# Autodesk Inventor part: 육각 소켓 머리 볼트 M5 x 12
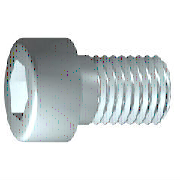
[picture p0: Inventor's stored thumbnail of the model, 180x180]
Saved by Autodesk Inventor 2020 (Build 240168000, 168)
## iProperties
Created: 2012-02
Part Number: 육각 소켓 머리 볼트 M5 x 12
Material: 강철, 연강
Description: 6각 소켓 머리 캡 나사
Document SubType Name: Modeling
Standard: ISO 4762
Designer: mdu-01
Standard Revision: Fourth edition 2004-03-01
Standards Organization: ISO
Language: ko-KR
Size Designation: M5 x 12
Categories: <MemberInstance><Categories><Category DisplayName="조임쇠" InternalName="e4da775c-781d-43d5-af7c-5136215cf5a6" Mnemonic="FSTN"><Category DisplayName="볼트" InternalN
Density: 7.86 g/cm^3
Appearance: 강철
Mass: 3.72825 g
Surface Area: 4.62573 cm^2
Volume: 0.474332 cm^3
Author: mdu-01
IsCustomPart: 1
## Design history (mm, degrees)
sketch "스케치1"
  geometry: L1 (-1.167, 0)-(12, 0); L2 (12, 0)-(12, 2.5); L3 (12, 2.5)-(2, 2.5); L4 (2, 2.5)-(1.509, 2.5); L5 (1.509, 2.5)-(0, 2.5); L6 (0, 2.5)-(0, 4.25); L7 (0, 4.25)-(-5, 4.25); L8 (-5, 4.25)-(-5, 2.309); L9 (-5, 2.309)-(-2.5, 2.309); L10 (-2.5, 2.309)-(-1.167, 0); L11 (-8.4, 0)-(15.4, 0) reference; L12 (0, -0.85)-(0, 5.1) reference; L13 (2, 2.5)-(0, 2.5)
  constraints: 22 end point, 6 parallel, 2 collinear, 2 perpendicular, 1 horizontal, 1 point on line
  dimensions: "d1" = 10 distance from line of L3.end L2 (= GEL); "d2" = 0.49086 distance of L4.end L3.end (computed from GAL); "d3" = 5 distance between parallel lines of L8 L6 (= KOH); "d4" = 2.5 distance of L8.end L9.end (= INTI); "d5" = 60 deg angle of L10 L1; "d6" = 5 diameter of L3 L1 (= GD); "d7" = 5 diameter of L5 L1 (= BDM); "d8" = 4.6188 diameter of L9 L1 (= 1.1547 x SW); "d9" = 8.5 diameter of L7 L1 (= KOD); "d26" = 12 distance between parallel lines of L12 L2 (= NLG)
revolve "본체" sketch "스케치1" stored, may be unused: angle "d10" = 90 deg
sketch "스케치2"
  geometry: L1 (0, -5.95)-(0, 5.95) reference; L2 (-5.95, 0)-(5.95, 0) reference; L3 (2.309, 0)-(1.155, -2); L4 (1.155, -2)-(-1.155, -2); L5 (-1.155, -2)-(-2.309, 0); L6 (-2.309, 0)-(-1.155, 2); L7 (-1.155, 2)-(1.155, 2); L8 (1.155, 2)-(2.309, 0); 2 further points
  constraints: 12 end point, 1 coincident, 1 horizontal alignment, 1 point on line, 12 other
extrude "슬롯" join sketch "스케치2" stored distance "d11" = 10; taper "d12" = 0 deg
workplane "Work Plane1"
fillet "Fillet2" dims "d30" = 0.1 (= R)
body "Solid1"
fillet "모깎기1" dims "d17" = 0.5 (= RR)
feature "스레드" dims "d13" = 10 (= GEL), "d14" = 0
chamfer "모따기1" distance "d15" = 0.49076 (= -0.5 x SPD + 0.5 x GD); stored, may be unused: second distance "d16" = 0.49076 (= GUL), angle "d27" = 45 deg
other parameters: "GD" = 5 [user parameter; used in 2 equation terms], "NLG" = 12 [user parameter; used in 1 equation term], "GEL" = 10 [user parameter; used in 2 equation terms], "KOD" = 8.5 [user parameter; used in 1 equation term], "KOH" = 5 [user parameter; used in 1 equation term], "INTI" = 2.5 [user parameter; used in 1 equation term], "GAL" = 0.49076 (= 0.61345 x PTC) [user parameter; used in 1 equation term], "GUL" = 0.49076 (= 0.61345 x PTC) [user parameter; used in 1 equation term], "BDM" = 5 (= NND) [user parameter; used in 1 equation term], "SW" = 4 [user parameter; used in 2 equation terms], "RR" = 0.5 [user parameter; used in 1 equation term], "SPD" = 4.01848 (= NND - 1.2269 x PTC) [user parameter; used in 1 equation term], "d19" = 0, "d28" = 0, "d29" = 0, "R" = 0.1 [user parameter; used in 1 equation term], "TOA" = 30 deg [user parameter], "GD1" = 4.01848 (= THREADDIA - 1.2269 x PTC) [user parameter], "THREADDIA" = 5 [user parameter; used in 1 equation term], "FAWI" = 45 deg [user parameter], "TPU" = 12.5 (computed from PTC) [user parameter], "PTC" = 0.8 [user parameter; used in 5 equation terms], "NND" = 5 [user parameter; used in 2 equation terms], "E0" = 4.62 (= 1.155 x SW) [user parameter]
